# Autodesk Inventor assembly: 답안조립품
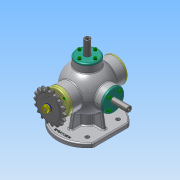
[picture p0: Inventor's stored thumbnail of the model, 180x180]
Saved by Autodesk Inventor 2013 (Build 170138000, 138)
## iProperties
Created: 2016-03
Part Number: 답안조립품
Document SubType Name: Assembly
Designer: Administrator
Mass: 3007.62 g
Surface Area: 2215.43 cm^2
Volume: 827.087 cm^3
Density: 3.6364 g/cm^3
Author: Administrator
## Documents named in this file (17)
- C:\Users\Administrator\Desktop\360308V1012\답안조립품.iam
- C:\Users\Administrator\Desktop\360308V1012\본체.ipt
- C:\Users\Administrator\Desktop\360308V1012\가변스프링.ipt
- C:\Users\Administrator\Desktop\360308V1012\너트-M8x1.ipt
- C:\Users\Administrator\Desktop\360308V1012\뒤커버.ipt
- C:\Users\Administrator\Desktop\360308V1012\베어링- 6202.ipt
- C:\Users\Administrator\Desktop\360308V1012\본체커버.ipt
- C:\Users\Administrator\Desktop\360308V1012\볼트 M4x0.7.ipt
- C:\Users\Administrator\Desktop\360308V1012\스프로킷.ipt
- C:\Users\Administrator\Desktop\360308V1012\슬라이드 커버.ipt
- C:\Users\Administrator\Desktop\360308V1012\슬라이드.ipt
- C:\Users\Administrator\Desktop\360308V1012\앞커버.ipt
- C:\Users\Administrator\Desktop\360308V1012\오일실.ipt
- C:\Users\Administrator\Desktop\360308V1012\와셔 8x17.ipt
- C:\Users\Administrator\Desktop\360308V1012\축.ipt
- C:\Users\Administrator\Desktop\360308V1012\키 3 x 3 x 12.ipt
- C:\Users\Administrator\Desktop\360308V1012\가변스프링1.ipt
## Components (19 placed, 3 different names)
1. 가변스프링:1
2. M4x0.7x12:17
3. 가변스프링1:1
4. M4x0.7x12:1
5. M4x0.7x12:3
6. M4x0.7x12:4
7. M4x0.7x12:5
8. M4x0.7x12:2
9. M4x0.7x12:6
10. M4x0.7x12:7
11. M4x0.7x12:8
12. M4x0.7x12:9
13. M4x0.7x12:11
14. M4x0.7x12:12
15. M4x0.7x12:13
16. M4x0.7x12:10
17. M4x0.7x12:14
18. M4x0.7x12:15
19. M4x0.7x12:16
